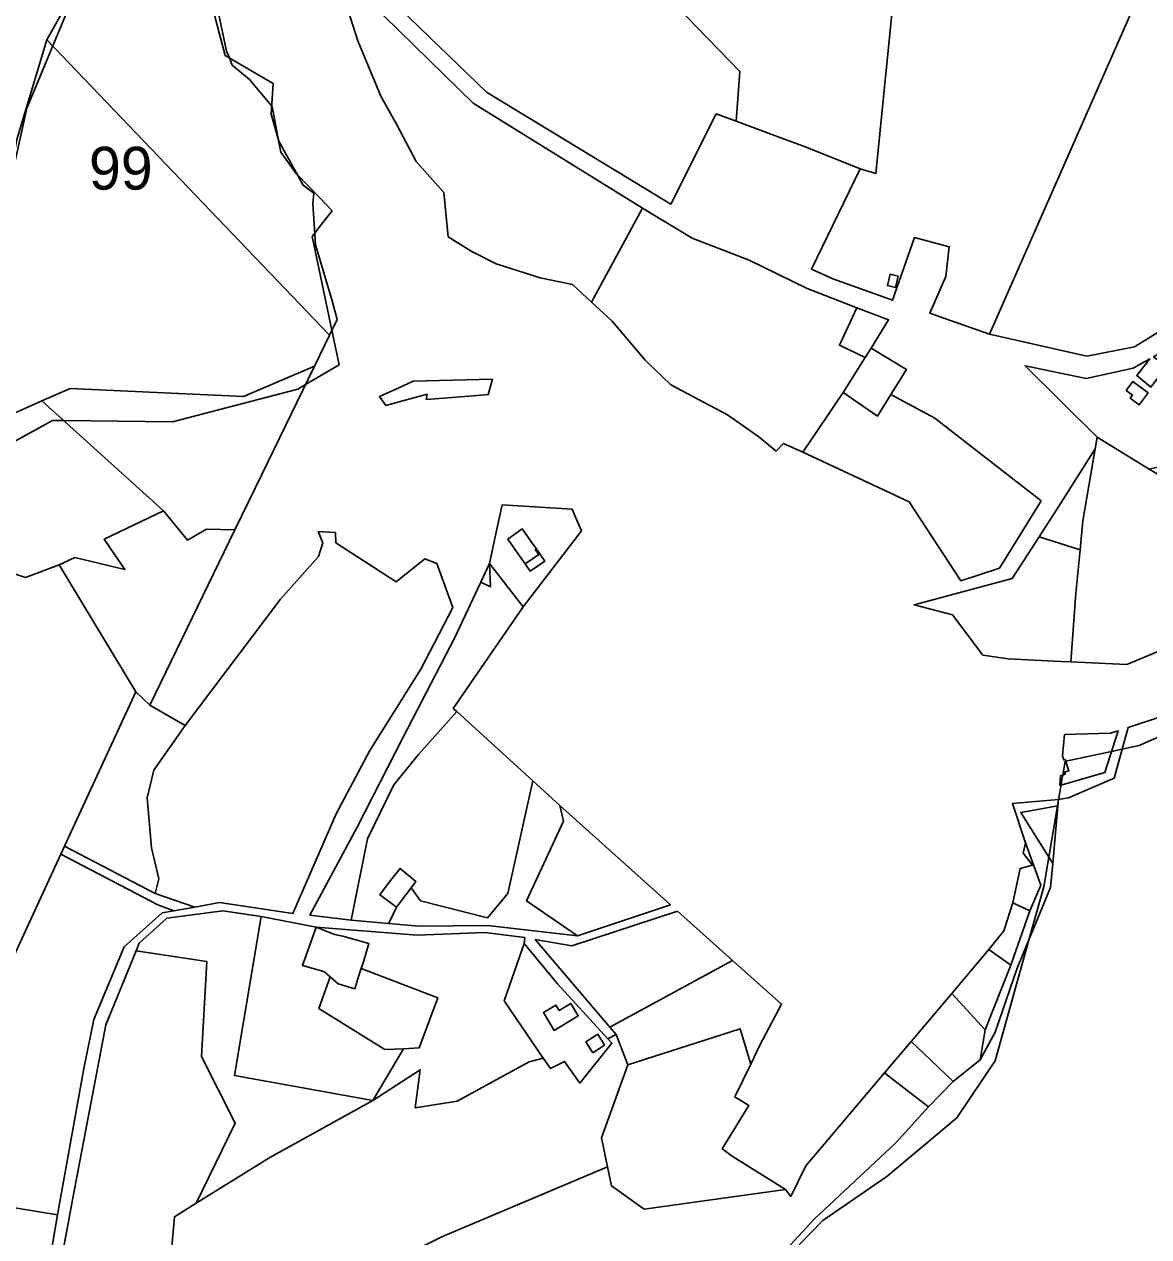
# Model space of a CAD drawing. Extents: x -477304 to -465429, y -1159113 to -1149210.
# Drawn here: x -476515 to -476120.7, y -1151655.2 to -1151230.1 of the extents above; entities that cross this region are included whole.
import ezdxf

# ---------------------------------------------------------------- set-up
doc = ezdxf.new("R2010")
doc.units = 0
for name, color, linetype in [('BPEJ_s', 7, 'Continuous'), ('orna_s', 7, 'Continuous'), ('PUPFL_s', 7, 'Continuous'), ('trav_porost_s', 7, 'Continuous'), ('zahrada_s', 7, 'Continuous')]:
    doc.layers.add(name, color=color, linetype=linetype)

msp = doc.modelspace()

# ---------------------------------------------------------------- linework, layer by layer
at = {"layer": 'BPEJ_s'}
for points in [[(-476453.59, -1151193.97), (-476444, -1151239.5), (-476443.03, -1151241.93), (-476442, -1151244.5), (-476436, -1151249.5), (-476428.17, -1151258.8), (-476428, -1151259), (-476425.78, -1151270.83), (-476425, -1151275), (-476420, -1151282), (-476419.23, -1151282.8), (-476411.44, -1151290.89), (-476411.36, -1151290.97), (-476407, -1151295.5), (-476410.69, -1151300.24), (-476413.07, -1151303.3), (-476414, -1151304.5), (-476407.06, -1151337.38), (-476404.5, -1151349.5), (-476416.31, -1151356.42), (-476419, -1151358), (-476463, -1151369.5), (-476501.11, -1151369.05), (-476505, -1151369), (-476526, -1151380.5)], [(-476526, -1151380.5), (-476505, -1151369), (-476501.11, -1151369.05), (-476463, -1151369.5), (-476419, -1151358), (-476416.31, -1151356.42), (-476404.5, -1151349.5), (-476407.06, -1151337.38), (-476414, -1151304.5), (-476413.07, -1151303.3), (-476410.69, -1151300.24), (-476407, -1151295.5), (-476411.36, -1151290.97), (-476411.44, -1151290.89), (-476419.23, -1151282.8), (-476420, -1151282), (-476425, -1151275), (-476425.78, -1151270.83), (-476428, -1151259), (-476428.17, -1151258.8), (-476436, -1151249.5), (-476442, -1151244.5), (-476443.03, -1151241.93), (-476444, -1151239.5), (-476453.59, -1151193.97)], [(-476522.5, -1151297.67), (-476514, -1151259.5), (-476504.97, -1151237.71), (-476495.6, -1151215.09)], [(-476495.6, -1151215.09), (-476504.97, -1151237.71), (-476514, -1151259.5), (-476522.5, -1151297.67)], [(-476114, -1151478.5), (-476124, -1151483), (-476129.99, -1151484.27), (-476133.69, -1151485.05), (-476149.8, -1151488.46), (-476150, -1151488.5), (-476150.82, -1151493.34), (-476151.12, -1151495.05), (-476151.42, -1151496.8), (-476152.29, -1151501.94), (-476152.46, -1151502.91), (-476152.55, -1151503.49), (-476152.66, -1151504.13), (-476155.72, -1151522.08), (-476157.5, -1151532.5), (-476162.57, -1151550.68), (-476174.5, -1151593.5), (-476188, -1151613.5), (-476212.5, -1151634), (-476235, -1151649.5), (-476300.35, -1151716.72)], [(-476114, -1151478.5), (-476124, -1151483), (-476129.99, -1151484.27), (-476133.69, -1151485.05), (-476149.8, -1151488.46), (-476150, -1151488.5), (-476150.82, -1151493.34), (-476151.12, -1151495.05), (-476151.42, -1151496.8), (-476152.29, -1151501.94), (-476152.46, -1151502.91), (-476152.55, -1151503.49), (-476152.66, -1151504.13), (-476155.72, -1151522.08), (-476157.5, -1151532.5), (-476162.57, -1151550.68), (-476174.5, -1151593.5), (-476188, -1151613.5), (-476212.5, -1151634), (-476235, -1151649.5), (-476300.35, -1151716.72)]]:
    msp.add_lwpolyline(points, dxfattribs=at)
at = {"layer": 'orna_s'}
for points in [[(-476094.22, -1151367.33), (-476101.11, -1151376.91), (-476108.85, -1151383.24), (-476120.51, -1151386.08), (-476138.73, -1151374.87), (-476164.06, -1151349.82), (-476142.61, -1151354.27), (-476126.17, -1151350.72), (-476120.34, -1151347.44), (-476124.85, -1151353.31), (-476119.99, -1151357.34), (-476114.49, -1151350.07), (-476118.96, -1151346.66), (-476096.81, -1151334.23), (-476090.63, -1151327.32), (-476086.31, -1151330.21)], [(-476128.65, -1151358.52), (-476126.42, -1151360.19), (-476127.18, -1151361.21), (-476124.02, -1151363.58), (-476120.84, -1151359.35), (-476126.23, -1151355.3)]]:
    msp.add_lwpolyline(points, close=True, dxfattribs=at)
at = {"layer": 'PUPFL_s'}
for points in [[(-476487.3, -1151200.26), (-476483.22, -1151185.06), (-476473.1, -1151168.36), (-476469.87, -1151171.32), (-476457.18, -1151169.82), (-476453.72, -1151189.09), (-476453.26, -1151205.74), (-476449.91, -1151220.65), (-476444.49, -1151241.07), (-476427.71, -1151250.94), (-476428.34, -1151261.66), (-476425.69, -1151271.16), (-476417.13, -1151286.58), (-476413.42, -1151289.39), (-476413.77, -1151292.95), (-476412.79, -1151307.45), (-476407, -1151327.11), (-476405.24, -1151333.64), (-476407.92, -1151339.15), (-476507.05, -1151235.54)], [(-476221.85, -1151280.79), (-476241.36, -1151273.02), (-476246.89, -1151270.96), (-476265.37, -1151264.1), (-476264.05, -1151246.63), (-476327.6, -1151181), (-476338.5, -1151170.07), (-476336.48, -1151168.29), (-476299.04, -1151188.16), (-476270.73, -1151198.19), (-476209.42, -1151213.67), (-476216.39, -1151282.46)], [(-476349.46, -1151314.1), (-476358.25, -1151309.7), (-476366.28, -1151304.61), (-476367.84, -1151289.16), (-476377.58, -1151278.27), (-476384.43, -1151265.14), (-476389.94, -1151255.37), (-476398, -1151235.98), (-476404.5, -1151215.31), (-476396.2, -1151183.22), (-476391.22, -1151220.46), (-476388.74, -1151227.24), (-476357.6, -1151257.79), (-476298.14, -1151294.63), (-476316.03, -1151327.52), (-476322.68, -1151321.3), (-476334.08, -1151319.06)], [(-476352.92, -1151253.9), (-476383.16, -1151224.7), (-476327.6, -1151181), (-476264.05, -1151246.63), (-476265.37, -1151264.1), (-476272.3, -1151261.53), (-476288.29, -1151293.22)], [(-476142.41, -1151346.43), (-476176.46, -1151338.75), (-476110.55, -1151189.06), (-476110.32, -1151333.77), (-476125.73, -1151343.18)], [(-476498.91, -1151357.8), (-476508.76, -1151362.14), (-476516.04, -1151365.35), (-476535.9, -1151374.23), (-476527.24, -1151341.98), (-476526.56, -1151319.8), (-476517.53, -1151270.58), (-476507.05, -1151235.54), (-476407.92, -1151339.15), (-476413.17, -1151349.96), (-476438.09, -1151360.65)], [(-476251.27, -1151379.83), (-476257.41, -1151374.76), (-476268.39, -1151367.02), (-476288.27, -1151356.51), (-476297.23, -1151347.85), (-476308.83, -1151334.25), (-476316.03, -1151327.52), (-476298.14, -1151294.63), (-476280.74, -1151305.08), (-476260.76, -1151312.82), (-476240.43, -1151322.7), (-476223, -1151329.58), (-476229.15, -1151342.62), (-476220.15, -1151346.98), (-476227.8, -1151359.23), (-476241.99, -1151380.13), (-476245.33, -1151378.56), (-476248.76, -1151377.11)], [(-476211.34, -1151317.75), (-476212.3, -1151321.73), (-476209.45, -1151322.42), (-476208.49, -1151318.44)], [(-476218.06, -1151343.63), (-476220.15, -1151346.98), (-476229.15, -1151342.62), (-476223, -1151329.58), (-476211.87, -1151333.69)], [(-476498.91, -1151357.8), (-476438.09, -1151360.65), (-476413.17, -1151349.96), (-476431.66, -1151388.01), (-476441.09, -1151407.41), (-476451.01, -1151407.18), (-476457.7, -1151410.99), (-476466.08, -1151400.65), (-476508.76, -1151362.14)], [(-476378.57, -1151355.2), (-476350.78, -1151354.57), (-476352.27, -1151359.96), (-476357.43, -1151360.35), (-476374, -1151361.61), (-476373.74, -1151359.85), (-476388.16, -1151363.74), (-476390.45, -1151360.63), (-476383.9, -1151357.64)], [(-476518.06, -1151422.87), (-476524.41, -1151432.91), (-476527.37, -1151434.94), (-476535.47, -1151440.51), (-476541.19, -1151444.44), (-476530.84, -1151423.65), (-476527.46, -1151402.22), (-476535.9, -1151374.23), (-476516.04, -1151365.35), (-476508.76, -1151362.14), (-476466.08, -1151400.65), (-476486.91, -1151410.58), (-476479.67, -1151421.31), (-476497.17, -1151417.09), (-476502.74, -1151419.65), (-476514.55, -1151424.08)], [(-476120.51, -1151386.08), (-476110.17, -1151392.12), (-476080.18, -1151416.71), (-476087.65, -1151426.89), (-476095.31, -1151435.71), (-476103.94, -1151444.53), (-476117.15, -1151449.84), (-476128.34, -1151454.57), (-476147.99, -1151453.67), (-476146.23, -1151429.57), (-476144.76, -1151414.4), (-476143.77, -1151404.2), (-476139.41, -1151378.98), (-476138.73, -1151374.87)], [(-476159.11, -1151409.78), (-476152.22, -1151399.07), (-476139.41, -1151378.98), (-476143.77, -1151404.2), (-476144.76, -1151414.4)], [(-476457.7, -1151410.99), (-476451.01, -1151407.18), (-476441.09, -1151407.41), (-476470.95, -1151468.84), (-476475.82, -1151464.15), (-476502.74, -1151419.65), (-476497.17, -1151417.09), (-476479.67, -1151421.31), (-476486.91, -1151410.58), (-476466.08, -1151400.65)], [(-476189.49, -1151437.15), (-476202.97, -1151433.65), (-476168.53, -1151424.41), (-476159.11, -1151409.78), (-476144.76, -1151414.4), (-476146.23, -1151429.57), (-476147.99, -1151453.67), (-476151.51, -1151453.53), (-476169.97, -1151452.53), (-476178.8, -1151451.27)], [(-476150.27, -1151479.13), (-476134.05, -1151478.67), (-476131.37, -1151477.85), (-476136.04, -1151492.37), (-476151.85, -1151496.93), (-476151.59, -1151493.59), (-476149.98, -1151493.06), (-476150.22, -1151492.32), (-476148.69, -1151491.82), (-476150, -1151487.85), (-476150.47, -1151488), (-476150.95, -1151486.55)], [(-476162.41, -1151540.93), (-476158.5, -1151531.95), (-476163.9, -1151517.11), (-476168.48, -1151503.29), (-476152.35, -1151501.95), (-476152.59, -1151504.12), (-476165.54, -1151506.44), (-476154.29, -1151524.36), (-476155.16, -1151532.71), (-476166.84, -1151561.05), (-476174.54, -1151583.47), (-476179.77, -1151593.15), (-476178.07, -1151582.66), (-476169.04, -1151559.94)], [(-476165.54, -1151506.44), (-476152.59, -1151504.12), (-476154.29, -1151524.36)], [(-476168.37, -1151538.1), (-476165.81, -1151526.07), (-476161.42, -1151524.88), (-476164.67, -1151520.74), (-476163.9, -1151517.11), (-476158.5, -1151531.95), (-476162.41, -1151540.93)], [(-476171.5, -1151547.98), (-476168.37, -1151538.1), (-476162.41, -1151540.93), (-476169.04, -1151559.94), (-476176.74, -1151554.51)], [(-476169.04, -1151559.94), (-476178.07, -1151582.66), (-476189.74, -1151569.88), (-476176.74, -1151554.51)], [(-476189.25, -1151600.8), (-476199.64, -1151590.85), (-476203.96, -1151586.68), (-476189.74, -1151569.88), (-476178.07, -1151582.66), (-476179.77, -1151593.15)], [(-476310.46, -1151630.66), (-476312.59, -1151620.45), (-476303.3, -1151594.9), (-476263.97, -1151582.26), (-476260.24, -1151594.65), (-476265.81, -1151606.18), (-476260.9, -1151609.11), (-476270.21, -1151624.34), (-476266.39, -1151627.18), (-476248.09, -1151638.64), (-476297.64, -1151645.54), (-476309.06, -1151637.37)], [(-476197.95, -1151609.65), (-476210, -1151600.25), (-476213.3, -1151597.71), (-476203.96, -1151586.68), (-476199.64, -1151590.85), (-476189.25, -1151600.8)]]:
    msp.add_lwpolyline(points, close=True, dxfattribs=at)
for points in [[(-476110.55, -1151189.06), (-476176.46, -1151338.75), (-476192.5, -1151333.12), (-476197.45, -1151331.4), (-476191.88, -1151318.54), (-476190.65, -1151308.1), (-476202.84, -1151304.89), (-476210.48, -1151326.87), (-476231.4, -1151319.39), (-476238.94, -1151315.96), (-476221.85, -1151280.79), (-476216.39, -1151282.46), (-476209.42, -1151213.67)], [(-476487.3, -1151200.26), (-476507.05, -1151235.54), (-476517.53, -1151270.58), (-476526.56, -1151319.8), (-476527.24, -1151341.98), (-476535.9, -1151374.23), (-476543.67, -1151377.6), (-476568.92, -1151391.8), (-476593.86, -1151367.91), (-476616.11, -1151342.35), (-476678.03, -1151267.64), (-476733.64, -1151200.69)], [(-476305.18, -1151721.96), (-476237.94, -1151648.97), (-476209.51, -1151622.34), (-476197.95, -1151609.65), (-476189.25, -1151600.8), (-476179.77, -1151593.15), (-476174.54, -1151583.47), (-476166.84, -1151561.05), (-476155.16, -1151532.71), (-476154.29, -1151524.36), (-476152.59, -1151504.12), (-476152.35, -1151501.95), (-476148.83, -1151501.25), (-476132.77, -1151494.37), (-476127.89, -1151476.65), (-476103.12, -1151468.47)], [(-476464.51, -1151673.11), (-476462.22, -1151648.14), (-476454.65, -1151643.45), (-476428.8, -1151627.42), (-476392.68, -1151607.39), (-476376.14, -1151596.62), (-476377.86, -1151610.01), (-476363.21, -1151607.69), (-476337.97, -1151593.82), (-476332.97, -1151592.56), (-476330.46, -1151596.25), (-476325.52, -1151593.7), (-476320.11, -1151601.3), (-476308.93, -1151587.29), (-476310.28, -1151585.82), (-476307.47, -1151584.26), (-476303.3, -1151594.9), (-476312.59, -1151620.45), (-476310.46, -1151630.66), (-476368.27, -1151655.04), (-476416.26, -1151678.78)], [(-476416.26, -1151678.78), (-476368.27, -1151655.04), (-476310.46, -1151630.66), (-476309.06, -1151637.37), (-476297.64, -1151645.54), (-476248.09, -1151638.64), (-476246.2, -1151641.06), (-476240.89, -1151630.32), (-476213.3, -1151597.71), (-476210, -1151600.25), (-476197.95, -1151609.65), (-476209.51, -1151622.34), (-476237.94, -1151648.97), (-476305.18, -1151721.96)]]:
    msp.add_lwpolyline(points, dxfattribs=at)
at = {"layer": 'trav_porost_s'}
for points in [[(-476218.06, -1151343.63), (-476205.62, -1151351.14), (-476211.09, -1151359.91), (-476215.81, -1151367.48), (-476227.8, -1151359.23), (-476220.15, -1151346.98)], [(-476172.97, -1151420.83), (-476186.54, -1151425.18), (-476204.63, -1151397.52), (-476241.99, -1151380.13), (-476227.8, -1151359.23), (-476215.81, -1151367.48), (-476211.09, -1151359.91), (-476195.67, -1151368.17), (-476158.41, -1151397.2)], [(-476322.81, -1151400.15), (-476321.73, -1151402.9), (-476319.55, -1151407.66), (-476340.01, -1151434.3), (-476351.87, -1151419.13), (-476349.48, -1151408.15), (-476347.4, -1151398.62)], [(-476471.81, -1151501.34), (-476469.49, -1151491.65), (-476458.51, -1151475.94), (-476425.06, -1151431.63), (-476411.74, -1151416.74), (-476410.27, -1151411.89), (-476411.88, -1151408), (-476405.83, -1151408.32), (-476405.66, -1151411.88), (-476384.58, -1151425.59), (-476374.53, -1151417.56), (-476370.34, -1151419.13), (-476364.66, -1151434.6), (-476375.88, -1151456.16), (-476393.84, -1151484.69), (-476405.64, -1151506.89), (-476420.76, -1151541.86), (-476446.44, -1151537.99), (-476455.14, -1151539.58), (-476469.1, -1151534.88), (-476467.78, -1151529.76), (-476470.36, -1151518.87)], [(-476335.47, -1151413.94), (-476336.73, -1151412.13), (-476340.32, -1151407.02), (-476345.43, -1151410.58), (-476341.84, -1151415.69), (-476339.31, -1151419.31), (-476337.53, -1151421.86), (-476332.43, -1151418.31)], [(-476335.84, -1151414.2), (-476335.47, -1151413.94), (-476332.43, -1151418.31), (-476337.53, -1151421.86), (-476339.31, -1151419.31), (-476334.58, -1151416.01)], [(-476385.35, -1151496.77), (-476394.58, -1151515.65), (-476400.35, -1151544.17), (-476414.78, -1151542.4), (-476398.28, -1151511.61), (-476382.2, -1151480.23), (-476363.96, -1151445.1), (-476354.92, -1151425.69), (-476351.53, -1151427.29), (-476351.87, -1151419.13), (-476340.01, -1151434.3), (-476364.54, -1151469.97), (-476363.29, -1151471.1), (-476376.67, -1151486.11)], [(-476351.87, -1151419.13), (-476351.53, -1151427.29), (-476354.92, -1151425.69)], [(-476471.81, -1151501.34), (-476470.36, -1151518.87), (-476467.78, -1151529.76), (-476469.1, -1151534.88), (-476500.84, -1151518.3), (-476475.82, -1151464.15), (-476470.95, -1151468.84), (-476458.51, -1151475.94), (-476469.49, -1151491.65)], [(-476376.67, -1151486.11), (-476363.29, -1151471.1), (-476336.63, -1151495.35), (-476345.38, -1151534.88), (-476352.58, -1151543.35), (-476376.01, -1151537.41), (-476379.31, -1151532.91), (-476377.6, -1151530.66), (-476383.16, -1151526.08), (-476387.02, -1151530.92), (-476390.28, -1151535.27), (-476389.48, -1151535.87), (-476386.31, -1151538.23), (-476384.84, -1151539.36), (-476384.38, -1151539.66), (-476386.78, -1151544.49), (-476387.24, -1151545.36), (-476400.35, -1151544.17), (-476394.58, -1151515.65), (-476385.35, -1151496.77)], [(-476386.78, -1151544.49), (-476384.38, -1151539.66), (-476381.13, -1151535.34), (-476379.31, -1151532.91), (-476376.01, -1151537.41), (-476352.58, -1151543.35), (-476345.38, -1151534.88), (-476336.63, -1151495.35), (-476327.18, -1151503.95), (-476325.86, -1151509.49), (-476338.8, -1151537.42), (-476320.96, -1151549.65), (-476352.56, -1151546.07), (-476376.66, -1151546.28), (-476387.24, -1151545.36)], [(-476327.18, -1151503.95), (-476288.41, -1151538.81), (-476320.96, -1151549.65), (-476338.8, -1151537.42), (-476325.86, -1151509.49)], [(-476502.12, -1151521.07), (-476500.84, -1151518.3), (-476469.1, -1151534.88), (-476455.14, -1151539.58), (-476462.49, -1151540.92), (-476468.09, -1151538.83)], [(-476462.49, -1151540.92), (-476466.54, -1151541.66), (-476479.92, -1151553.56), (-476490.58, -1151578.98), (-476494.1, -1151596.2), (-476503.33, -1151647.45), (-476524.84, -1151643.95), (-476543.36, -1151636.12), (-476551.48, -1151627.89), (-476522.73, -1151565.68), (-476502.12, -1151521.07), (-476468.09, -1151538.83)], [(-476445.33, -1151540.87), (-476431.91, -1151542.86), (-476441.28, -1151598.67), (-476392.68, -1151607.39), (-476428.8, -1151627.42), (-476454.65, -1151643.45), (-476441.01, -1151615.33), (-476452.81, -1151592), (-476450.94, -1151558.69), (-476475.74, -1151554.89), (-476474.69, -1151552.21), (-476464.98, -1151543.5)], [(-476285.88, -1151541.09), (-476266.65, -1151558.38), (-476309.58, -1151581.76), (-476335.79, -1151551), (-476322.91, -1151553.24)], [(-476346.66, -1151572.47), (-476332.97, -1151592.56), (-476337.97, -1151593.82), (-476363.21, -1151607.69), (-476377.86, -1151610.01), (-476376.14, -1151596.62), (-476392.68, -1151607.39), (-476381.95, -1151589.26), (-476376.49, -1151589), (-476370, -1151571.46), (-476396.83, -1151561.16), (-476395.98, -1151558.77), (-476394.17, -1151552.42), (-476403.26, -1151549.83), (-476406.21, -1151549.25), (-476412.65, -1151546.62), (-476377.17, -1151549.4), (-476353.46, -1151548.47), (-476339.44, -1151550.28), (-476339.71, -1151552.33)], [(-476308.93, -1151587.29), (-476320.11, -1151601.3), (-476325.52, -1151593.7), (-476330.46, -1151596.25), (-476332.97, -1151592.56), (-476346.66, -1151572.47), (-476339.71, -1151552.33), (-476327.96, -1151566.52), (-476310.28, -1151585.82)], [(-476481.93, -1151733.58), (-476496.85, -1151768.85), (-476505.9, -1151766.98), (-476504.39, -1151749.29), (-476494.04, -1151719.38), (-476500.49, -1151683.72), (-476501.27, -1151659.92), (-476497.63, -1151640.34), (-476486.3, -1151580.91), (-476475.74, -1151554.89), (-476450.94, -1151558.69), (-476452.81, -1151592), (-476441.01, -1151615.33), (-476454.65, -1151643.45), (-476462.22, -1151648.14), (-476464.51, -1151673.11), (-476470.23, -1151684.64), (-476468.05, -1151700.08), (-476476.42, -1151724.22)], [(-476263.97, -1151582.26), (-476303.3, -1151594.9), (-476307.47, -1151584.26), (-476309.58, -1151581.76), (-476266.65, -1151558.38), (-476249.44, -1151573.62), (-476257.07, -1151588.07), (-476260.24, -1151594.65)], [(-476411.64, -1151575.12), (-476407.7, -1151564.07), (-476404.93, -1151566.54), (-476399.02, -1151568.22), (-476397.69, -1151563.56), (-476396.83, -1151561.16), (-476370, -1151571.46), (-476376.49, -1151589), (-476381.95, -1151589.26), (-476388.48, -1151589.57)], [(-476329.17, -1151582.84), (-476320.68, -1151577.78), (-476323.35, -1151573.36), (-476327.41, -1151575.81), (-476328.53, -1151573.95), (-476332.86, -1151576.52)], [(-476315.64, -1151590.66), (-476311.46, -1151587.97), (-476313.9, -1151584.2), (-476318.08, -1151586.88)], [(-476503.32, -1151690.11), (-476508.52, -1151687.43), (-476531.56, -1151676.3), (-476555.98, -1151650.09), (-476543.36, -1151636.12), (-476524.84, -1151643.95), (-476503.33, -1151647.45), (-476505.77, -1151661.87), (-476504.73, -1151682.44)]]:
    msp.add_lwpolyline(points, close=True, dxfattribs=at)
msp.add_lwpolyline([(-476518.06, -1151422.87), (-476514.55, -1151424.08), (-476502.74, -1151419.65), (-476475.82, -1151464.15), (-476500.84, -1151518.3), (-476502.12, -1151521.07), (-476522.73, -1151565.68)], dxfattribs=at)
at = {"layer": 'zahrada_s'}
msp.add_lwpolyline([(-476392.68, -1151607.39), (-476441.28, -1151598.67), (-476431.91, -1151542.86), (-476412.65, -1151546.62), (-476417.4, -1151560.03), (-476409.88, -1151562.14), (-476407.7, -1151564.07), (-476411.64, -1151575.12), (-476388.48, -1151589.57), (-476381.95, -1151589.26)], close=True, dxfattribs=at)

# ---------------------------------------------------------------- texts
at = {"layer": 'BPEJ_s'}
msp.add_text('99', height=15, dxfattribs=at).set_placement((-476492.25, -1151288.08))

doc.saveas('drawing.dxf')
